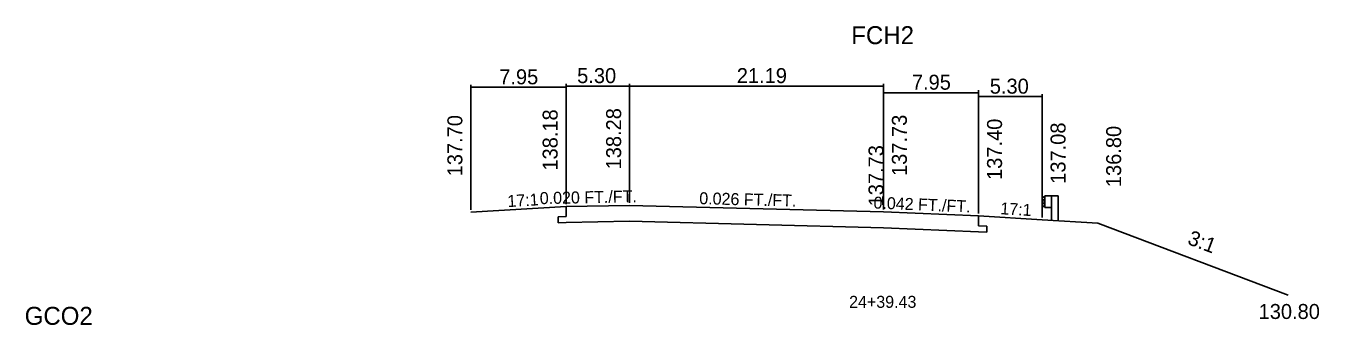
# Model space of a CAD drawing. Extents: x -14327 to 8886, y -10 to 39048.
# Drawn here: x 3147.7 to 3255.6, y 11035.3 to 11060.3 of the extents above; entities that cross this region are included whole.
import ezdxf

# ---------------------------------------------------------------- set-up
doc = ezdxf.new("R2010")
doc.units = 0
doc.layers.add('Level 20', color=7, linetype='Continuous')
doc.layers.add('RD_XS_TX_Baseline', color=7, linetype='Continuous')

msp = doc.modelspace()

# ---------------------------------------------------------------- linework, layer by layer
at = {"layer": 'Level 20'}
for p, q in [((3192.72, 11055.43), (3192.72, 11045.38)), ((3198.02, 11055.43), (3198.02, 11045.48)), ((3219.21, 11055.43), (3219.21, 11044.93)), ((3184.77, 11055.33), (3184.77, 11044.9)), ((3192.72, 11055.13), (3184.77, 11055.13)), ((3192.72, 11055.33), (3192.72, 11045.38)), ((3192.72, 11055.23), (3198.02, 11055.23)), ((3198.02, 11055.23), (3219.21, 11055.23)), ((3219.21, 11054.88), (3219.21, 11044.93)), ((3219.21, 11054.68), (3227.15, 11054.68)), ((3227.15, 11054.88), (3227.15, 11044.6)), ((3227.15, 11054.55), (3227.15, 11044.6)), ((3227.15, 11054.35), (3232.45, 11054.35)), ((3232.45, 11054.55), (3232.45, 11044.28)), ((3232.47, 11045.9), (3232.59, 11045.99)), ((3232.47, 11045.8), (3232.59, 11045.71)), ((3232.6, 11046), (3232.68, 11046.01)), ((3232.68, 11046.07), (3232.68, 11045.1)), ((3232.68, 11046.07), (3233.23, 11046.07)), ((3233.23, 11044.08), (3233.23, 11046.07)), ((3233.23, 11046.07), (3233.79, 11046.07)), ((3233.79, 11044.08), (3233.79, 11046.07)), ((3192.72, 11045.18), (3184.77, 11044.7)), ((3192.72, 11045.18), (3198.02, 11045.28)), ((3192.72, 11045.18), (3192.72, 11044.34)), ((3198.02, 11045.28), (3219.21, 11044.73)), ((3219.21, 11044.73), (3227.15, 11044.4)), ((3232.47, 11045.37), (3232.59, 11045.46)), ((3232.47, 11045.27), (3232.59, 11045.18)), ((3232.6, 11045.17), (3232.68, 11045.16)), ((3232.61, 11045.66), (3232.61, 11045.51)), ((3232.68, 11045.1), (3233.23, 11045.1)), ((3192.72, 11044.34), (3192.06, 11044.33)), ((3192.06, 11044.33), (3192.06, 11043.83)), ((3192.06, 11043.83), (3192.72, 11043.84)), ((3198.02, 11043.95), (3192.72, 11043.84)), ((3219.21, 11043.4), (3198.02, 11043.95)), ((3227.15, 11044.4), (3227.15, 11043.57)), ((3227.15, 11044.4), (3232.45, 11044.08)), ((3227.15, 11043.57), (3227.82, 11043.55)), ((3227.82, 11043.55), (3227.82, 11043.05)), ((3232.45, 11044.08), (3237.09, 11043.8)), ((3237.09, 11043.8), (3252.98, 11037.8)), ((3227.15, 11043.07), (3219.21, 11043.4)), ((3227.82, 11043.05), (3227.15, 11043.07))]:
    msp.add_line(p, q, dxfattribs=at)
for centre, radius, start, end in [((3232.52, 11045.85), 0.0651, 129.0336, 230.9663), ((3232.6, 11045.97), 0.026, 90, 129.0505), ((3232.54, 11045.66), 0.0651, 0, 45), ((3232.52, 11045.32), 0.0651, 129.0336, 230.9663), ((3232.54, 11045.51), 0.0651, 302.9895, 0), ((3232.6, 11045.2), 0.026, 230.9496, 270)]:
    msp.add_arc(centre, radius, start, end, dxfattribs=at)

# ---------------------------------------------------------------- texts
for s, height, p in [('FCH2', 1.5, (3216.52, 11058.73)), ('7.95', 1.25, (3187.15, 11055.38)), ('5.30', 1.25, (3193.65, 11055.48)), ('21.19', 1.25, (3206.97, 11055.48)), ('7.95', 1.25, (3221.58, 11054.93)), ('5.30', 1.25, (3228.08, 11054.6)), ('24+39.43', 1, (3216.34, 11036.73)), ('130.80', 1.25, (3250.51, 11035.8))]:
    msp.add_text(s, height=height, dxfattribs=at).set_placement(p)
for s, height, rotation, p in [('138.28', 1.25, 90, (3197.32, 11048.28)), ('137.70', 1.25, 90, (3184.07, 11047.7)), ('138.18', 1.25, 90, (3192.02, 11048.18)), ('137.73', 1.25, 90, (3221.16, 11047.73)), ('137.40', 1.25, 90, (3229.1, 11047.4)), ('137.08', 1.25, 90, (3234.4, 11047.08)), ('136.80', 1.25, 90, (3239.04, 11046.8)), (' 137.73', 1.25, 90, (3219.21, 11044.73)), ('17:1', 1, 3.4568, (3187.86, 11045.13)), ('0.020 FT./FT.', 1, 1.152, (3190.54, 11045.38)), ('0.026 FT./FT.', 1, 358.518, (3203.83, 11045.38)), ('0.042 FT./FT.', 1, 357.6113, (3218.36, 11045.02)), ('17:1', 1, 356.5432, (3228.94, 11044.54)), ('3:1', 1.25, 339.3165, (3244.5, 11042.07))]:
    msp.add_text(s, height=height, rotation=rotation, dxfattribs=at).set_placement(p)
at = {"layer": 'RD_XS_TX_Baseline'}
msp.add_text('GCO2', height=1.5, dxfattribs=at).set_placement((3147.55, 11035.31))

doc.saveas('drawing.dxf')
